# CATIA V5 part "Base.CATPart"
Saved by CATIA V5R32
Part number: Part1
Bounding box of the stored display mesh (mm): x -50 to 50, y -25 to 25, z 0 to 50
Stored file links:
  D:\PROJECTS\Project 2022\CATIA V5 6R 2022\Resources\Part Files\c12_catia_v5_6r2022_prt\c12_catia_v5-6r2022 figr_12-8\Base.CATPart
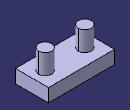
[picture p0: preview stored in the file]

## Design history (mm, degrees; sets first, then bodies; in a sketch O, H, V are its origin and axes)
Body1 (main body)
  Sketch1 on xy-plane, origin (0, 0, 0), H (1, 0, 0), V (0, 1, 0)
    line L1 (50, 25) -> (50, -25)
    line L2 (50, -25) -> (-50, -25)
    line L3 (-50, -25) -> (-50, 25)
    line L4 (-50, 25) -> (50, 25)
    circle A1 centre (-30, 0) radius 10
    point P5 (-30, 0)
    circle A2 centre (30, 0) radius 10
    length L2 = 100
    length L1 = 50
    radius A1 = 10
    distance P5 V = 30
    vertical: L1 V, L3 V
    horizontal: L2 H, L4 H
    equidistance: L1 L3 O, L2 L4 O
    coincidence: P5 H
    symmetry: A1 A2 V
  MultiPad1: profile Sketch1, domains (length 20; length 50; length 50)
